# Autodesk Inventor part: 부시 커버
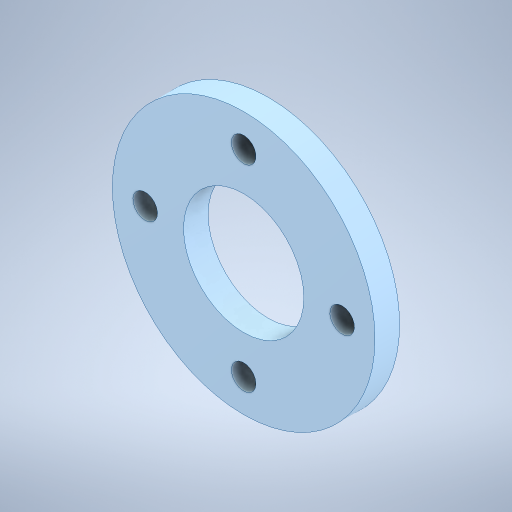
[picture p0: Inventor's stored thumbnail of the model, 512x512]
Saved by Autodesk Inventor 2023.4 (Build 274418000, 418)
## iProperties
Created: 2024-05
Part Number: 부시 커버
Material: 강철, 연강
Document SubType Name: Modeling
Designer: user
Density: 7.85 g/cm^3
Appearance: 기본값
Author: jhkim
Sending System: Autodesk Inventor 2025
Preprocessor: ST-DEVELOPER v20
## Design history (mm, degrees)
feature "솔리드1"
node "솔리드2"
